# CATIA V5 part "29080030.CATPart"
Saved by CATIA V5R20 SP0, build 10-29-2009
Part number: 29080030
Definition: NONE
Nomenclature: 29080030
Source: Unknown
Description: 29080030
Bounding box of the stored display mesh (mm): x -15 to 44.548, y -54 to 88.548, z -44 to 44
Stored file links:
  C:\Users\Utente\Desktop\IO LAVORO\3D X SITO CF\X SITO\PLASTICA\RF1\29080030.CATPart
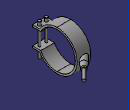
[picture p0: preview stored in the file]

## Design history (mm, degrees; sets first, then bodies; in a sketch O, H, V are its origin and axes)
Body1 "29080030" (main body)
  Solid1: solid without history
